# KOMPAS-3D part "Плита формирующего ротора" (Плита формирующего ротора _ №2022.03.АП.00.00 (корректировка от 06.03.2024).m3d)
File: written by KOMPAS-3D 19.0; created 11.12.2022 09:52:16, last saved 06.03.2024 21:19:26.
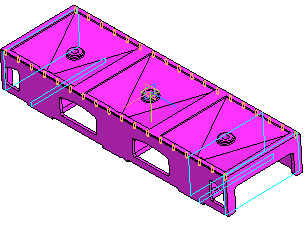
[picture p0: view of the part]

Document properties: Полное имя файла: G:\Кемерово чертежи\3. Плита формующего ротора\Плита формирующего ротора _ №2022.03.АП.00.00 (корректировка от 06.03.2024).m3d

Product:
- Part/product: Плита формирующего ротора
    Материал: СЧ35  ГОСТ 1412-85 (density 7400 kg/m3)
    Масса: 152.603
  - Body: Тело 1
      Масса: 152.608

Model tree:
1. Эскиз:1
2. Элемент выдавливания:1
     Расстояние 1 = 1260
3. Смещенная плоскость:1  (with: Элемент выдавливания:1)
     Расстояние = 16
4. Эскиз:2  (with: Элемент выдавливания:1)
5. Элемент выдавливания:2
     Расстояние 2 = 1228
6. Эскиз:3  (with: Элемент выдавливания:1)
7. Элемент выдавливания:3
     Расстояние 2 = 4
8. Эскиз:4  (with: Элемент выдавливания:3)
9. Элемент выдавливания:4
     Расстояние 2 = 36
10. Эскиз:5  (with: Элемент выдавливания:4)
11. Эскиз:6  (with: Элемент выдавливания:3)
12. Элемент по сечениям:1
13. Эскиз:7  (with: Элемент выдавливания:4)
14. Эскиз:8  (with: Элемент выдавливания:3)
15. Элемент по сечениям:2
16. Эскиз:9  (with: Элемент выдавливания:4)
17. Эскиз:10  (with: Элемент выдавливания:3)
18. Элемент по сечениям:3
19. Эскиз:11  (with: Элемент выдавливания:1)
20. Элемент выдавливания:5
     Расстояние 2 = 173
21. Эскиз:12  (with: Элемент выдавливания:1)
22. Элемент выдавливания:6  (with: Элемент выдавливания:2)
     Расстояние 1 = -134.023
23. Эскиз:13  (with: Элемент выдавливания:1)
24. Элемент выдавливания:7
     Расстояние 1 = 10; Расстояние 2 = 12
25. Смещенная плоскость:2  (with: Элемент выдавливания:1)
     Расстояние = 210
26. Эскиз:14
27. Элемент вращения:1
     Угол 1 = 360
28. Эскиз:15
29. Элемент вращения:2
     Угол 1 = 360
30. Эскиз:16
31. Элемент выдавливания:8
     Расстояние 1 = 16
32. Массив по сетке:2  (with: Эскиз:14, Элемент вращения:1, Эскиз:15, Элемент вращения:2, Эскиз:16, Элемент выдавливания:8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)  (labels: v263_2_1_v213; v263_2_1_v214; v263_2_1_v215; Толщина стенки 1)  (3 pattern instances)
     Шаг 1 = 420; Угол раствора = 90
33. Эскиз:17  (with: Элемент выдавливания:7)
34. Элемент выдавливания:9
     Расстояние 2 = 5
35. Смещенная плоскость:3  (with: Элемент выдавливания:7)
     Расстояние = 20
36. Эскиз:18  (with: Элемент выдавливания:7, Элемент выдавливания:1)
37. Элемент вращения:3
     Угол 1 = 360
38. Массив по сетке:1  (with: Элемент вращения:3, Смещенная плоскость:3, Элемент выдавливания:7)  (4 pattern instances)
     Шаг 1 = 85; Угол раствора = 90; Геометрический массив = 128
39. Смещенная плоскость:4  (with: Элемент выдавливания:7)
     Расстояние = 20
40. Эскиз:19  (with: Элемент выдавливания:7, Элемент выдавливания:1)
41. Элемент вращения:4
     Угол 1 = 360
42. Массив по сетке:3  (with: Эскиз:19, Элемент выдавливания:7, Элемент выдавливания:1, Элемент вращения:4)  (labels: v366_2_1_v355; v366_2_1_v356; v366_2_1_v357; Толщина стенки 1)  (4 pattern instances)
     Шаг 1 = 85; Угол раствора = 90
43. Скругление:1  (with: Элемент выдавливания:7, Элемент выдавливания:2)
     Радиус = 4
44. Скругление:2  (with: Элемент выдавливания:5, Элемент выдавливания:7, Элемент выдавливания:8)
     Радиус = 4
45. Скругление:3  (with: Элемент выдавливания:8)
     Радиус = 4
46. Скругление:7  (with: Элемент выдавливания:8)
     Радиус = 4
47. Скругление:8  (with: Элемент выдавливания:8)
     Радиус = 4
48. Скругление:9  (with: Элемент выдавливания:8, Скругление:2, Скругление:8, Элемент выдавливания:6, Скругление:3)
     Радиус = 4
49. Скругление:10  (with: Элемент выдавливания:7, Элемент выдавливания:8)
     Радиус = 4
50. Скругление:11  (with: Элемент выдавливания:6)
     Радиус = 4
51. Скругление:12  (with: Элемент выдавливания:8, Элемент выдавливания:7, Элемент выдавливания:5)
     Радиус = 4
52. Скругление:13  (with: Элемент выдавливания:6)
     Радиус = 4
53. Скругление:14  (with: Элемент выдавливания:7, Элемент выдавливания:8, Элемент выдавливания:5)
     Радиус = 4
54. Скругление:15  (with: Элемент выдавливания:6)
     Радиус = 4
55. Эскиз:20  (with: Элемент выдавливания:1)
56. Элемент выдавливания:10
     Расстояние 2 = 25
57. Эскиз:21  (with: Элемент выдавливания:1, Элемент выдавливания:7)
58. Элемент выдавливания:11
     Расстояние 2 = 25
59. Смещенная плоскость:5  (with: Элемент выдавливания:1)
     Расстояние = 18
60. Эскиз:22  (with: Элемент выдавливания:1)
61. Элемент вращения:5
     Угол 1 = 360
62. Скругление:16  (with: Элемент вращения:1, Элемент выдавливания:5)
     Радиус = 4
63. Эскиз:23  (with: Элемент выдавливания:1)
64. Элемент выдавливания:12  (with: Массив по сетке:2, Элемент вращения:5, Смещенная плоскость:5, Элемент выдавливания:1)  (36 pattern instances)
     Расстояние 2 = 195; Шаг 1 = 72; Угол раствора = 90; Шаг 2 = 378
65. Элемент выдавливания:13  (with: Элемент выдавливания:1)
     Расстояние 1 = 3
66. Элемент выдавливания:14  (with: Элемент выдавливания:1)
     Расстояние 1 = 2
67. Элемент выдавливания:15  (with: Элемент выдавливания:1)
     Расстояние 1 = 2
68. Условное изображение резьбы:4  (with: Элемент вращения:5, Элемент выдавливания:13)  (labels: M8; cil0_24705-2004 coarse)
     Длина резьбы = 25; Шаг резьбы = 1.25; Номинальный диаметр резьбы = 8
69. Подгонка:3  (with: Элемент вращения:5)
70. Условное изображение резьбы:5  (with: Элемент вращения:5, Элемент выдавливания:13)  (labels: M8; cil0_24705-2004 coarse)
     Длина резьбы = 25; Шаг резьбы = 1.25; Номинальный диаметр резьбы = 8
71. Подгонка:4  (with: Элемент вращения:5)
72. Условное изображение резьбы:6  (with: Элемент вращения:5, Элемент выдавливания:13)  (labels: M8; cil0_24705-2004 coarse)
     Длина резьбы = 25; Шаг резьбы = 1.25; Номинальный диаметр резьбы = 8
73. Подгонка:5  (with: Элемент вращения:5)
74. Условное изображение резьбы:7  (with: Элемент вращения:5, Элемент выдавливания:13)  (labels: M8; cil0_24705-2004 coarse)
     Длина резьбы = 25; Шаг резьбы = 1.25; Номинальный диаметр резьбы = 8
75. Подгонка:6  (with: Элемент вращения:5)
76. Условное изображение резьбы:8  (with: Элемент вращения:5, Элемент выдавливания:13)  (labels: M8; cil0_24705-2004 coarse)
     Длина резьбы = 25; Шаг резьбы = 1.25; Номинальный диаметр резьбы = 8
77. Подгонка:7  (with: Элемент вращения:5)
78. Условное изображение резьбы:9  (with: Элемент вращения:5, Элемент выдавливания:13)  (labels: M8; cil0_24705-2004 coarse)
     Длина резьбы = 25; Шаг резьбы = 1.25; Номинальный диаметр резьбы = 8
79. Подгонка:8  (with: Элемент вращения:5)
80. Условное изображение резьбы:10  (with: Элемент вращения:5, Элемент выдавливания:13)  (labels: M8; cil0_24705-2004 coarse)
     Длина резьбы = 25; Шаг резьбы = 1.25; Номинальный диаметр резьбы = 8
81. Подгонка:9  (with: Элемент вращения:5)
82. Условное изображение резьбы:11  (with: Элемент вращения:5, Элемент выдавливания:13)  (labels: M8; cil0_24705-2004 coarse)
     Длина резьбы = 25; Шаг резьбы = 1.25; Номинальный диаметр резьбы = 8
83. Подгонка:10  (with: Элемент вращения:5)
84. Условное изображение резьбы:12  (with: Элемент вращения:5, Элемент выдавливания:13)  (labels: M8; cil0_24705-2004 coarse)
     Длина резьбы = 25; Шаг резьбы = 1.25; Номинальный диаметр резьбы = 8
85. Подгонка:11  (with: Элемент вращения:5)
86. Условное изображение резьбы:13  (with: Элемент вращения:5, Элемент выдавливания:13)  (labels: M8; cil0_24705-2004 coarse)
     Длина резьбы = 25; Шаг резьбы = 1.25; Номинальный диаметр резьбы = 8
87. Подгонка:12  (with: Элемент вращения:5)
88. Условное изображение резьбы:14  (with: Элемент вращения:5, Элемент выдавливания:13)  (labels: M8; cil0_24705-2004 coarse)
     Длина резьбы = 25; Шаг резьбы = 1.25; Номинальный диаметр резьбы = 8
89. Подгонка:13  (with: Элемент вращения:5)
90. Условное изображение резьбы:15  (with: Элемент вращения:5, Элемент выдавливания:13)  (labels: M8; cil0_24705-2004 coarse)
     Длина резьбы = 25; Шаг резьбы = 1.25; Номинальный диаметр резьбы = 8
91. Подгонка:14  (with: Элемент вращения:5)
92. Условное изображение резьбы:16  (with: Элемент вращения:5, Элемент выдавливания:13)  (labels: M8; cil0_24705-2004 coarse)
     Длина резьбы = 25; Шаг резьбы = 1.25; Номинальный диаметр резьбы = 8
93. Подгонка:15  (with: Элемент вращения:5)
94. Условное изображение резьбы:17  (with: Элемент вращения:5, Элемент выдавливания:13)  (labels: M8; cil0_24705-2004 coarse)
     Длина резьбы = 25; Шаг резьбы = 1.25; Номинальный диаметр резьбы = 8
95. Подгонка:16  (with: Элемент вращения:5)
96. Условное изображение резьбы:18  (with: Элемент вращения:5, Элемент выдавливания:13)  (labels: M8; cil0_24705-2004 coarse)
     Длина резьбы = 25; Шаг резьбы = 1.25; Номинальный диаметр резьбы = 8
97. Подгонка:17  (with: Элемент вращения:5)
98. Условное изображение резьбы:19  (with: Элемент вращения:5, Элемент выдавливания:13)  (labels: M8; cil0_24705-2004 coarse)
     Длина резьбы = 25; Шаг резьбы = 1.25; Номинальный диаметр резьбы = 8
99. Подгонка:18  (with: Элемент вращения:5)
100. Условное изображение резьбы:20  (with: Элемент вращения:5, Элемент выдавливания:13)  (labels: M8; cil0_24705-2004 coarse)
     Длина резьбы = 25; Шаг резьбы = 1.25; Номинальный диаметр резьбы = 8
101. Подгонка:19  (with: Элемент вращения:5)
102. Условное изображение резьбы:21  (with: Элемент вращения:5, Элемент выдавливания:13)  (labels: M8; cil0_24705-2004 coarse)
     Длина резьбы = 25; Шаг резьбы = 1.25; Номинальный диаметр резьбы = 8
103. Подгонка:20  (with: Элемент вращения:5)
104. Условное изображение резьбы:22  (with: Элемент вращения:5, Элемент выдавливания:13)  (labels: M8; cil0_24705-2004 coarse)
     Длина резьбы = 25; Шаг резьбы = 1.25; Номинальный диаметр резьбы = 8
105. Подгонка:21  (with: Элемент вращения:5)
106. Условное изображение резьбы:23  (with: Элемент вращения:5, Элемент выдавливания:13)  (labels: M8; cil0_24705-2004 coarse)
     Длина резьбы = 25; Шаг резьбы = 1.25; Номинальный диаметр резьбы = 8
107. Подгонка:22  (with: Элемент вращения:5)
108. Условное изображение резьбы:24  (with: Элемент вращения:5, Элемент выдавливания:13)  (labels: M8; cil0_24705-2004 coarse)
     Длина резьбы = 25; Шаг резьбы = 1.25; Номинальный диаметр резьбы = 8
109. Подгонка:23  (with: Элемент вращения:5)
110. Условное изображение резьбы:25  (with: Элемент вращения:5, Элемент выдавливания:13)  (labels: M8; cil0_24705-2004 coarse)
     Длина резьбы = 25; Шаг резьбы = 1.25; Номинальный диаметр резьбы = 8
111. Подгонка:24  (with: Элемент вращения:5)
112. Условное изображение резьбы:26  (with: Элемент вращения:5, Элемент выдавливания:13)  (labels: M8; cil0_24705-2004 coarse)
     Длина резьбы = 25; Шаг резьбы = 1.25; Номинальный диаметр резьбы = 8
113. Подгонка:25  (with: Элемент вращения:5)
114. Условное изображение резьбы:27  (with: Элемент вращения:5, Элемент выдавливания:13)  (labels: M8; cil0_24705-2004 coarse)
     Длина резьбы = 25; Шаг резьбы = 1.25; Номинальный диаметр резьбы = 8
115. Подгонка:26  (with: Элемент вращения:5)
116. Условное изображение резьбы:28  (with: Элемент вращения:5, Элемент выдавливания:13)  (labels: M8; cil0_24705-2004 coarse)
     Длина резьбы = 25; Шаг резьбы = 1.25; Номинальный диаметр резьбы = 8
117. Подгонка:27  (with: Элемент вращения:5)
118. Условное изображение резьбы:29  (with: Элемент вращения:5, Элемент выдавливания:13)  (labels: M8; cil0_24705-2004 coarse)
     Длина резьбы = 25; Шаг резьбы = 1.25; Номинальный диаметр резьбы = 8
119. Подгонка:28  (with: Элемент вращения:5)
120. Условное изображение резьбы:30  (with: Элемент вращения:5, Элемент выдавливания:13)  (labels: M8; cil0_24705-2004 coarse)
     Длина резьбы = 25; Шаг резьбы = 1.25; Номинальный диаметр резьбы = 8
121. Подгонка:29  (with: Элемент вращения:5)
122. Условное изображение резьбы:31  (with: Элемент вращения:5, Элемент выдавливания:13)  (labels: M8; cil0_24705-2004 coarse)
     Длина резьбы = 25; Шаг резьбы = 1.25; Номинальный диаметр резьбы = 8
123. Подгонка:30  (with: Элемент вращения:5)
124. Условное изображение резьбы:32  (with: Элемент вращения:5, Элемент выдавливания:13)  (labels: M8; cil0_24705-2004 coarse)
     Длина резьбы = 25; Шаг резьбы = 1.25; Номинальный диаметр резьбы = 8
125. Подгонка:31  (with: Элемент вращения:5)
126. Условное изображение резьбы:33  (with: Элемент вращения:5, Элемент выдавливания:13)  (labels: M8; cil0_24705-2004 coarse)
     Длина резьбы = 25; Шаг резьбы = 1.25; Номинальный диаметр резьбы = 8
127. Подгонка:32  (with: Элемент вращения:5)
128. Условное изображение резьбы:34  (with: Элемент вращения:5, Элемент выдавливания:13)  (labels: M8; cil0_24705-2004 coarse)
     Длина резьбы = 25; Шаг резьбы = 1.25; Номинальный диаметр резьбы = 8
129. Подгонка:33  (with: Элемент вращения:5)
130. Условное изображение резьбы:35  (with: Элемент вращения:5, Элемент выдавливания:13)  (labels: M8; cil0_24705-2004 coarse)
     Длина резьбы = 25; Шаг резьбы = 1.25; Номинальный диаметр резьбы = 8
131. Подгонка:34  (with: Элемент вращения:5)
132. Условное изображение резьбы:36  (with: Элемент вращения:5, Элемент выдавливания:13)  (labels: M8; cil0_24705-2004 coarse)
     Длина резьбы = 25; Шаг резьбы = 1.25; Номинальный диаметр резьбы = 8
133. Подгонка:35  (with: Элемент вращения:5)
134. Условное изображение резьбы:37  (with: Элемент вращения:5, Элемент выдавливания:13)  (labels: M8; cil0_24705-2004 coarse)
     Длина резьбы = 25; Шаг резьбы = 1.25; Номинальный диаметр резьбы = 8
135. Подгонка:36  (with: Элемент вращения:5)
136. Условное изображение резьбы:38  (with: Элемент вращения:5, Элемент выдавливания:13)  (labels: M8; cil0_24705-2004 coarse)
     Длина резьбы = 25; Шаг резьбы = 1.25; Номинальный диаметр резьбы = 8
137. Подгонка:37  (with: Элемент вращения:5)
138. Условное изображение резьбы:39  (with: Элемент вращения:5, Элемент выдавливания:13)  (labels: M8; cil0_24705-2004 coarse)
     Длина резьбы = 25; Шаг резьбы = 1.25; Номинальный диаметр резьбы = 8
139. Подгонка:38  (with: Элемент вращения:5)
140. Фаска:2  (with: Элемент выдавливания:13)  (labels: СЧ35  ГОСТ 1412-85)
     Угол = 45; Длина 1 = 1.25; Длина 2 = 1.25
